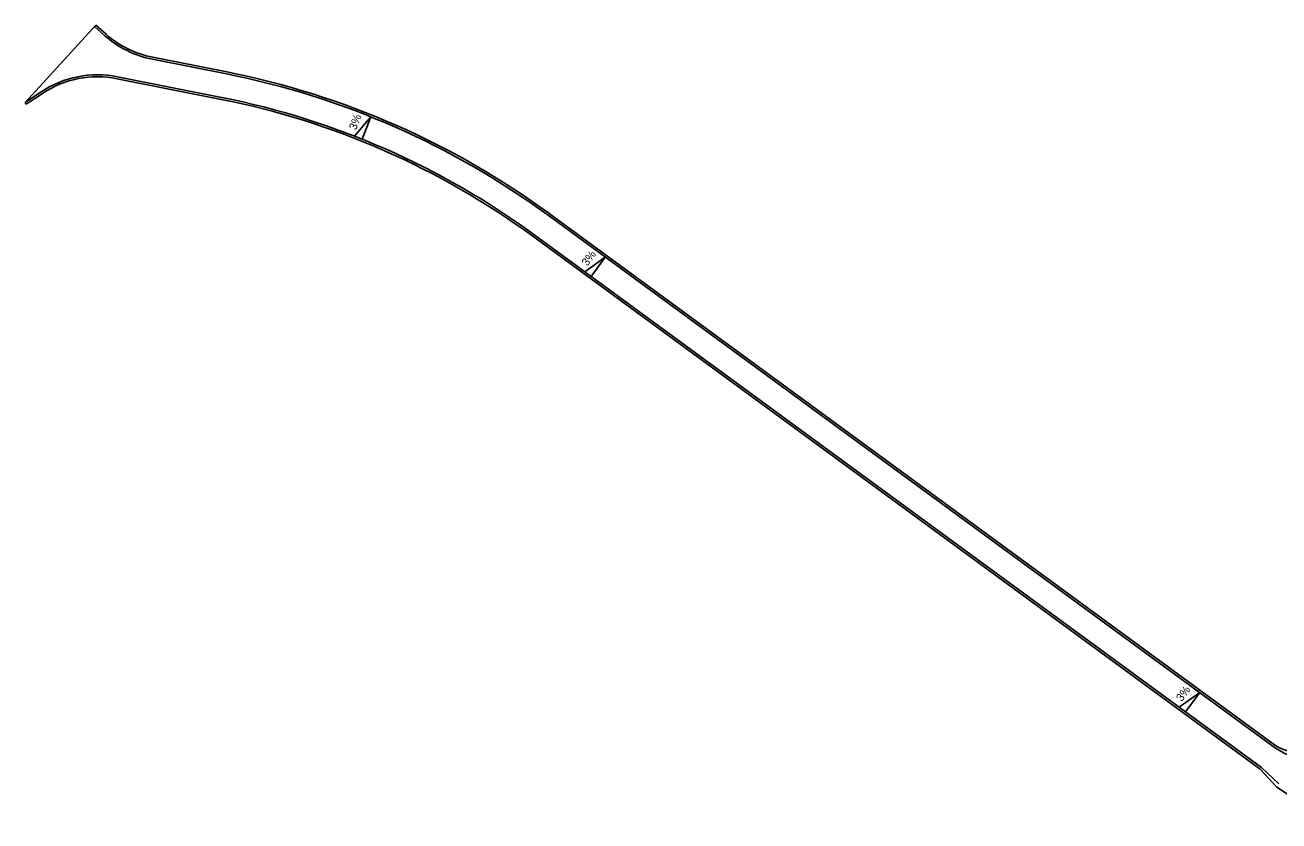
# Model space of a CAD drawing. Extents: x -540257 to -536057, y -1045049 to -1042079.
# Drawn here: x -538580.7 to -538424, y -1043042.8 to -1042943.3 of the extents above; entities that cross this region are included whole.
import ezdxf

# ---------------------------------------------------------------- set-up
doc = ezdxf.new("R2010")
doc.units = 0
doc.layers.add('Nová vrstva (3)', color=7, linetype='Continuous')
doc.layers.add('Nová vrstva (5)', color=7, linetype='Continuous')

msp = doc.modelspace()

# ---------------------------------------------------------------- linework, layer by layer
at = {"layer": 'Nová vrstva (3)'}
for p, q in [((-538580.69, -1042952.97), (-538571.85, -1042943.3)), ((-538572.02, -1042943.49), (-538570.72, -1042944.63)), ((-538571.85, -1042943.3), (-538570.56, -1042944.44)), ((-538555.53, -1042949.4), (-538564.78, -1042947.56)), ((-538555.48, -1042949.15), (-538564.73, -1042947.32)), ((-538556.16, -1042952.59), (-538569.19, -1042950)), ((-538556.12, -1042952.34), (-538569.15, -1042949.76)), ((-538580.69, -1042952.97), (-538578.66, -1042951.63)), ((-538580.55, -1042953.18), (-538578.53, -1042951.84)), ((-538580.69, -1042952.97), (-538580.55, -1042953.18)), ((-538426.29, -1043036.3), (-538424.24, -1043038.56)), ((-538423.96, -1043038.14), (-538426.15, -1043036.09))]:
    msp.add_line(p, q, dxfattribs=at)
for points in [[(-538424.37, -1043033.67), (-538515.31, -1042967.07)], [(-538424.68, -1043033.14), (-538515.16, -1042966.87)], [(-538426.29, -1043036.3), (-538517.23, -1042969.69)], [(-538426.15, -1043036.09), (-538517.08, -1042969.49)], [(-538417.87, -1043042.78), (-538424.23, -1043038.56)]]:
    msp.add_lwpolyline(points, dxfattribs=at)
for centre, radius, start, end in [((-538562.3, -1042935.06), 12.75, 228.6452, 258.7797), ((-538562.3, -1042935.06), 12.5, 228.6452, 258.7797), ((-538571.63, -1042962.26), 12.75, 78.7797, 123.5073), ((-538571.63, -1042962.26), 12.5, 78.7797, 123.5073), ((-538575.28, -1043048.96), 101.5, 53.7797, 78.7797), ((-538575.28, -1043048.96), 101.75, 53.7797, 78.7797), ((-538575.28, -1043048.96), 98.25, 53.7797, 78.7797), ((-538575.28, -1043048.96), 98.5, 53.7797, 78.7797), ((-538421.14, -1043028.3), 6, 233.7797, 335.7344), ((-538420.83, -1043028.83), 6, 233.7797, 336.3607)]:
    msp.add_arc(centre, radius, start, end, dxfattribs=at)
at = {"layer": 'Nová vrstva (5)'}
for points in [[(-538537.45, -1042954.77), (-538538.57, -1042957.56), (-538539.5, -1042957.18)], [(-538508.16, -1042972.31), (-538509.93, -1042974.73), (-538510.74, -1042974.14)], [(-538433.85, -1043026.73), (-538435.63, -1043029.15), (-538436.43, -1043028.56)]]:
    msp.add_lwpolyline(points, close=True, dxfattribs=at)

# ---------------------------------------------------------------- texts
for rotation, p in [(68.1555, (-538539.33, -1042956.49)), (53.7797, (-538510.4, -1042973.5)), (53.7797, (-538436.1, -1043027.93))]:
    msp.add_text('3%', height=1, rotation=rotation, dxfattribs=at).set_placement(p)

doc.saveas('drawing.dxf')
